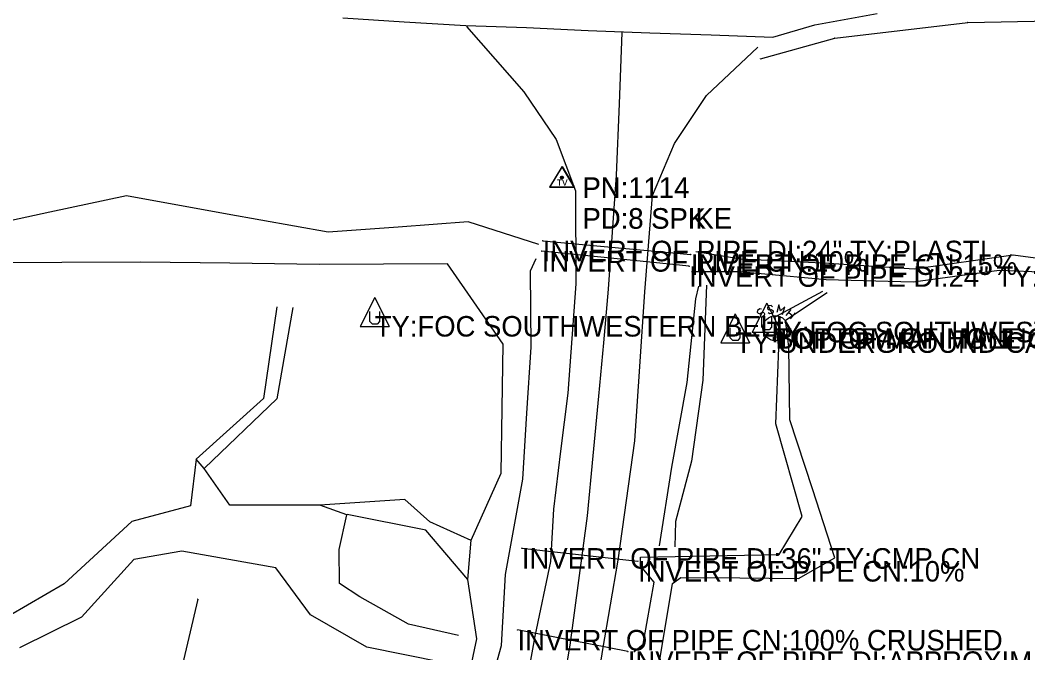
# Model space of a CAD drawing. Extents: x 976456 to 985170, y 1525951 to 1527080.
# Drawn here: x 977697.7 to 977943.1, y 1526330.3 to 1526484.4 of the extents above; entities that cross this region are included whole.
import ezdxf

# ---------------------------------------------------------------- set-up
doc = ezdxf.new("R2010")
doc.units = 0
for name, color, linetype in [('S_BREAKLINE', 7, 'Continuous'), ('S_CROSS_DRAIN', 7, 'Continuous'), ('S_CROSS_DRAIN_ANNOT', 7, 'Continuous'), ('S_DITCHLINE', 7, 'Continuous'), ('S_DRG_PT_SYM', 7, 'Continuous'), ('S_EDGE_PAVEMENT', 7, 'Continuous'), ('S_GRD_PT_SYM', 7, 'Continuous'), ('S_GUARDRAIL', 7, 'Continuous'), ('S_MANHOLE_ANNOT', 7, 'Continuous'), ('S_PAVEMENT_CROWN', 7, 'Continuous'), ('S_RDW_PT_SYM', 7, 'Continuous'), ('S_SANITARY_SEWER', 7, 'Continuous'), ('S_SECONDARY_CTL', 7, 'Continuous'), ('S_SECONDARY_CTL_ANNOT', 7, 'Continuous'), ('S_SHOULDER', 7, 'Continuous'), ('S_UNDERGROUND_CABLE', 7, 'Continuous'), ('S_UTILITY_POLE_ANNOT', 7, 'Continuous'), ('S_UTL_PT_SYM', 7, 'Continuous')]:
    doc.layers.add(name, color=color, linetype=linetype)

msp = doc.modelspace()

# ---------------------------------------------------------------- linework, layer by layer
at = {"layer": 'S_BREAKLINE'}
msp.add_line((977740.93, 1526343.34), (977728.22, 1526288.65), dxfattribs=at)
at = {"layer": 'S_CROSS_DRAIN'}
for p, q in [((977824.96, 1526430.66), (977861.01, 1526427.33)), ((977860.63, 1526424.44), (977824.71, 1526428.13)), ((977819.89, 1526355.78), (977848.16, 1526352.64)), ((977845.69, 1526330.63), (977818.83, 1526335.85))]:
    msp.add_line(p, q, dxfattribs=at)
at = {"layer": 'S_DITCHLINE'}
for points in [[(977824.01, 1526429.76), (977806.83, 1526435.23), (977789.76, 1526433.97), (977772.69, 1526432.72), (977748.13, 1526437.15), (977723.57, 1526441.59), (977704.89, 1526437.58), (977686.21, 1526433.57)], [(978029.35, 1526436.22), (978017.97, 1526427.26), (978002.04, 1526427.7), (977986.11, 1526428.13), (977972.06, 1526422.75), (977955.81, 1526424.94), (977939.55, 1526427.12), (977915.43, 1526423.73), (977894.67, 1526425.09), (977873.2, 1526426.21), (977862.22, 1526427.92)], [(977861.21, 1526423.15), (977872.89, 1526423.19), (977894, 1526421.24), (977915.17, 1526420.65), (977936.11, 1526423.49), (977952.01, 1526422.85), (977967.92, 1526422.22), (977976.62, 1526420.59), (977994.52, 1526423.18), (978016.54, 1526422.99), (978031.46, 1526432.01)], [(977803.87, 1526309.92), (977808.88, 1526333.69), (977806.74, 1526348.14), (977807.54, 1526357.7), (977814.88, 1526374.06), (977815.09, 1526389.76), (977815.3, 1526405.46), (977801.81, 1526425), (977786.16, 1526424.94), (977770.5, 1526424.88), (977748.75, 1526425.18), (977727.01, 1526425.48), (977707.82, 1526425.38), (977688.64, 1526425.27)], [(977808.39, 1526308.74), (977814.91, 1526332.03), (977815.86, 1526349.35), (977820.11, 1526372.61), (977821.12, 1526388.66), (977822.13, 1526404.71), (977822, 1526423.32), (977823.34, 1526426.37)], [(977853.4, 1526356.35), (977856.43, 1526375.48), (977860.13, 1526396.13), (977862.25, 1526416.51), (977862.98, 1526419.61)], [(977864.85, 1526419.8), (977863.93, 1526396.73), (977861.18, 1526376.96), (977857.26, 1526362.29), (977857.14, 1526356.11)], [(977847.16, 1526330.52), (977849.42, 1526332.41), (977852.1, 1526347.5), (977848.81, 1526351.45), (977848.81, 1526353.59), (977865.66, 1526353.92), (977882.51, 1526354.26), (977888.16, 1526363.46), (977881.77, 1526386.04), (977882.5, 1526404.6), (977881.56, 1526412.16), (977893.17, 1526418.4)], [(977847.83, 1526301.04), (977850.45, 1526313.6), (977853.06, 1526326.17), (977856.57, 1526347.16), (977858.63, 1526348.63), (977872.94, 1526348.52), (977887.25, 1526348.41), (977896.12, 1526353.4), (977890.63, 1526370.24), (977885.14, 1526387.07), (977884.92, 1526404.81), (977884.08, 1526411.28), (977894.26, 1526418.08)], [(977760.18, 1526414.57), (977756.94, 1526392.26), (977740.53, 1526377.44)], [(977764.09, 1526414.37), (977760.22, 1526392.12), (977742.56, 1526375.25)], [(977804.41, 1526334.54), (977792.3, 1526337.23), (977780.42, 1526343.88), (977775.43, 1526347.17), (977775.37, 1526355.41), (977777.24, 1526363.86), (977770.71, 1526366.26), (977748.79, 1526366.23), (977742.52, 1526375.22), (977740.54, 1526377.45), (977739.18, 1526366.08), (977724.89, 1526362.3), (977708.4, 1526347.08), (977690.48, 1526336.73)], [(977807.52, 1526357.61), (977797.49, 1526362.17), (977791.37, 1526367.64), (977770.7, 1526366.24)], [(977806.74, 1526348.14), (977796.52, 1526360.14), (977777.31, 1526363.99)], [(977804.61, 1526322.43), (977800.62, 1526327.94), (977782.14, 1526331.65), (977768.39, 1526339.53), (977759.99, 1526350.97), (977737.1, 1526355.06), (977725.38, 1526353.03), (977712.6, 1526339), (977697.5, 1526331.47)]]:
    msp.add_lwpolyline(points, dxfattribs=at)
at = {"layer": 'S_DRG_PT_SYM'}
for points in [[(977824.96, 1526430.66), (977824.96, 1526430.71), (977824.96, 1526430.66), (977824.91, 1526430.66), (977824.96, 1526430.66), (977824.96, 1526430.61), (977824.96, 1526430.66), (977825.01, 1526430.66)], [(977824.71, 1526428.13), (977824.71, 1526428.18), (977824.71, 1526428.13), (977824.66, 1526428.13), (977824.71, 1526428.13), (977824.71, 1526428.08), (977824.71, 1526428.13), (977824.76, 1526428.13)], [(977861.01, 1526427.33), (977861.01, 1526427.38), (977861.01, 1526427.33), (977860.96, 1526427.33), (977861.01, 1526427.33), (977861.01, 1526427.28), (977861.01, 1526427.33), (977861.06, 1526427.33)], [(977860.63, 1526424.44), (977860.63, 1526424.49), (977860.63, 1526424.44), (977860.58, 1526424.44), (977860.63, 1526424.44), (977860.63, 1526424.39), (977860.63, 1526424.44), (977860.68, 1526424.44)], [(977819.89, 1526355.78), (977819.89, 1526355.83), (977819.89, 1526355.78), (977819.84, 1526355.78), (977819.89, 1526355.78), (977819.89, 1526355.73), (977819.89, 1526355.78), (977819.94, 1526355.78)], [(977848.16, 1526352.64), (977848.16, 1526352.69), (977848.16, 1526352.64), (977848.11, 1526352.64), (977848.16, 1526352.64), (977848.16, 1526352.59), (977848.16, 1526352.64), (977848.21, 1526352.64)], [(977818.83, 1526335.85), (977818.83, 1526335.9), (977818.83, 1526335.85), (977818.78, 1526335.85), (977818.83, 1526335.85), (977818.83, 1526335.8), (977818.83, 1526335.85), (977818.88, 1526335.85)], [(977845.69, 1526330.63), (977845.69, 1526330.68), (977845.69, 1526330.63), (977845.64, 1526330.63), (977845.69, 1526330.63), (977845.69, 1526330.58), (977845.69, 1526330.63), (977845.74, 1526330.63)]]:
    msp.add_lwpolyline(points, dxfattribs=at)
at = {"layer": 'S_EDGE_PAVEMENT'}
for points in [[(977806.37, 1526482.87), (977820.39, 1526466.97), (977828.21, 1526455.31), (977832.92, 1526442.85), (977832.99, 1526420.15), (977832.01, 1526406.85), (977831.04, 1526393.54), (977829.31, 1526379.42), (977827.58, 1526365.3), (977826.83, 1526352.54), (977823.07, 1526334.32), (977820.44, 1526319.89), (977820.11, 1526318.04)], [(977836.99, 1526314.48), (977839.59, 1526331.09), (977843.36, 1526352.86), (977845.38, 1526367.38), (977847.41, 1526381.91), (977848.61, 1526400.06), (977849.81, 1526418.21), (977851.7, 1526441.64), (977857.03, 1526454.35), (977864.88, 1526466), (977877.36, 1526477.82)]]:
    msp.add_lwpolyline(points, dxfattribs=at)
at = {"layer": 'S_GRD_PT_SYM'}
msp.add_lwpolyline([(977740.93, 1526343.34), (977740.93, 1526343.39), (977740.93, 1526343.34), (977740.88, 1526343.34), (977740.93, 1526343.34), (977740.93, 1526343.29), (977740.93, 1526343.34), (977740.98, 1526343.34)], dxfattribs=at)
at = {"layer": 'S_GUARDRAIL'}
for p, q in [((977896.06, 1526480.01), (977928.47, 1526483.86)), ((977928.47, 1526483.86), (977954.58, 1526484.3)), ((977878.03, 1526474.98), (977896.06, 1526480.01))]:
    msp.add_line(p, q, dxfattribs=at)
at = {"layer": 'S_PAVEMENT_CROWN'}
msp.add_lwpolyline([(977844.21, 1526481.41), (977843.54, 1526464.03), (977842.87, 1526446.65), (977841.9, 1526432.77), (977840.93, 1526418.89), (977839.74, 1526405.83), (977838.55, 1526392.78), (977837.18, 1526378.23), (977835.8, 1526363.67), (977833.69, 1526347.92), (977831.58, 1526332.17), (977829.1, 1526317.87), (977826.61, 1526303.58), (977821.41, 1526279.65), (977816.2, 1526255.72), (977811.81, 1526238.51), (977807.43, 1526221.29), (977803.88, 1526208.91), (977800.34, 1526196.52), (977796.79, 1526184.14), (977793.25, 1526171.75), (977786.88, 1526150.07), (977780.5, 1526128.38)], dxfattribs=at)
at = {"layer": 'S_RDW_PT_SYM'}
for points in [[(977928.47, 1526483.86), (977928.47, 1526483.91), (977928.47, 1526483.86), (977928.42, 1526483.86), (977928.47, 1526483.86), (977928.47, 1526483.81), (977928.47, 1526483.86), (977928.52, 1526483.86)], [(977896.06, 1526480.01), (977896.06, 1526480.06), (977896.06, 1526480.01), (977896.01, 1526480.01), (977896.06, 1526480.01), (977896.06, 1526479.96), (977896.06, 1526480.01), (977896.11, 1526480.01)], [(977878.03, 1526474.98), (977878.03, 1526475.03), (977878.03, 1526474.98), (977877.98, 1526474.98), (977878.03, 1526474.98), (977878.03, 1526474.93), (977878.03, 1526474.98), (977878.08, 1526474.98)]]:
    msp.add_lwpolyline(points, dxfattribs=at)
at = {"layer": 'S_SANITARY_SEWER'}
for p, q in [((977877.29, 1526413.66), (977877.21, 1526413.27)), ((977877.21, 1526413.27), (977877.4, 1526413)), ((977877.83, 1526414.04), (977877.29, 1526413.66)), ((977877.4, 1526413), (977877.83, 1526412.88)), ((977878.26, 1526413.97), (977877.83, 1526414.04)), ((977877.83, 1526412.88), (977878.37, 1526413.23)), ((977878.37, 1526412.07), (977877.98, 1526412.15)), ((977878.37, 1526413.23), (977878.84, 1526413.15)), ((977878.91, 1526412.46), (977878.37, 1526412.07)), ((977878.84, 1526413.15), (977878.99, 1526412.88)), ((977878.99, 1526412.88), (977878.91, 1526412.46)), ((977884.26, 1526412.42), (977885.5, 1526413.89)), ((977884.92, 1526413.19), (977885.89, 1526412.38)), ((977886.47, 1526413.08), (977885.23, 1526411.6))]:
    msp.add_line(p, q, dxfattribs=at)
for points in [[(977880.93, 1526414.59), (977880.58, 1526414.86), (977879.92, 1526414.78), (977879.69, 1526414.43), (977879.73, 1526414.12), (977880.08, 1526413.81), (977880.7, 1526413.93), (977881.08, 1526413.62), (977881.12, 1526413.31), (977880.85, 1526412.92), (977880.23, 1526412.84), (977879.88, 1526413.11)], [(977883.37, 1526412.73), (977883.91, 1526414.59), (977882.87, 1526413.58), (977882.48, 1526415.01), (977881.94, 1526413.15)]]:
    msp.add_lwpolyline(points, dxfattribs=at)
msp.add_circle((977881.61, 1526409.35), 3.05, dxfattribs=at)
at = {"layer": 'S_SECONDARY_CTL'}
for p, q in [((977829.67, 1526448.72), (977826.66, 1526443.76)), ((977829.67, 1526448.72), (977832.62, 1526443.76)), ((977829.63, 1526448.69), (977826.62, 1526443.74)), ((977829.63, 1526448.69), (977832.57, 1526443.74)), ((977826.62, 1526443.74), (977832.57, 1526443.74)), ((977826.66, 1526443.76), (977832.62, 1526443.76))]:
    msp.add_line(p, q, dxfattribs=at)
for centre, radius in [((977829.63, 1526446.08), 0.311), ((977829.67, 1526446.11), 0.311), ((977829.63, 1526446.08), 0.183), ((977829.67, 1526446.11), 0.183), ((977829.63, 1526446.08), 0.103), ((977829.67, 1526446.11), 0.103)]:
    msp.add_circle(centre, radius, dxfattribs=at)
at = {"layer": 'S_SHOULDER'}
msp.add_lwpolyline([(977776.26, 1526484.99), (977791.24, 1526483.97), (977806.22, 1526483.07), (977821.05, 1526482.58), (977836.03, 1526481.89), (977851.02, 1526481.29), (977866.01, 1526480.8), (977881, 1526480.22), (977891.25, 1526483.24), (977906.37, 1526485.99)], dxfattribs=at)
at = {"layer": 'S_UNDERGROUND_CABLE'}
for p, q in [((977784.05, 1526416.86), (977780.52, 1526409.77)), ((977784.05, 1526416.86), (977787.54, 1526409.77)), ((977879.51, 1526415.45), (977875.99, 1526408.36)), ((977879.51, 1526415.45), (977883, 1526408.36)), ((977782.85, 1526411.01), (977782.85, 1526413.45)), ((977785.21, 1526413.45), (977785.21, 1526411.01)), ((977871.84, 1526412.89), (977868.31, 1526405.8)), ((977871.84, 1526412.89), (977875.33, 1526405.8)), ((977878.31, 1526409.6), (977878.31, 1526412.04)), ((977880.68, 1526412.04), (977880.68, 1526409.6)), ((977780.52, 1526409.77), (977787.54, 1526409.77)), ((977783.47, 1526410.35), (977782.85, 1526411.01)), ((977784.67, 1526410.35), (977783.47, 1526410.35)), ((977785.21, 1526411.01), (977784.67, 1526410.35)), ((977870.64, 1526407.04), (977870.64, 1526409.48)), ((977873, 1526409.48), (977873, 1526407.04)), ((977878.93, 1526408.94), (977878.31, 1526409.6)), ((977880.68, 1526409.6), (977880.13, 1526408.94)), ((977871.26, 1526406.38), (977870.64, 1526407.04)), ((977873, 1526407.04), (977872.46, 1526406.38)), ((977875.99, 1526408.36), (977883, 1526408.36)), ((977880.13, 1526408.94), (977878.93, 1526408.94)), ((977868.31, 1526405.8), (977875.33, 1526405.8)), ((977872.46, 1526406.38), (977871.26, 1526406.38))]:
    msp.add_line(p, q, dxfattribs=at)
at = {"layer": 'S_UTL_PT_SYM'}
msp.add_lwpolyline([(977881.61, 1526409.35), (977881.61, 1526409.4), (977881.61, 1526409.35), (977881.56, 1526409.35), (977881.61, 1526409.35), (977881.61, 1526409.3), (977881.61, 1526409.35), (977881.66, 1526409.35)], dxfattribs=at)

# ---------------------------------------------------------------- texts
at = {"layer": 'S_CROSS_DRAIN_ANNOT'}
for s, p in [('INVERT OF PIPE DI:24" TY:PLASTI', (977824.96, 1526425.66)), ('INVERT OF PIPE CN:10%', (977824.71, 1526423.13)), ('INVERT OF PIPE CN:15%', (977861.01, 1526422.33)), ('INVERT OF PIPE DI:24" TY:PLASTI', (977860.63, 1526419.44)), ('INVERT OF PIPE DI:36" TY:CMP CN', (977819.89, 1526350.78)), ('INVERT OF PIPE CN:10%', (977848.16, 1526347.64)), ('INVERT OF PIPE CN:100% CRUSHED', (977818.83, 1526330.85)), ('INVERT OF PIPE DI:APPROXIMATE 1', (977845.69, 1526325.63))]:
    msp.add_text(s, height=5, dxfattribs=at).set_placement(p)
at = {"layer": 'S_MANHOLE_ANNOT'}
for s in ['TOP OF MANHOLE', 'BOTTOM OF MANHOLE']:
    msp.add_text(s, height=5, dxfattribs=at).set_placement((977881.61, 1526404.35))
at = {"layer": 'S_SECONDARY_CTL'}
for p in [(977828.42, 1526444.07), (977828.47, 1526444.1)]:
    msp.add_text('TV', height=1.5, rotation=360, dxfattribs=at).set_placement(p)
at = {"layer": 'S_SECONDARY_CTL_ANNOT'}
for s, p in [('PN:1114', (977834.63, 1526441.08)), ('PN:1114', (977834.67, 1526441.11)), ('PD:8 SPK', (977834.63, 1526433.58)), ('PD:8 SPIKE', (977834.67, 1526433.61))]:
    msp.add_text(s, height=5, dxfattribs=at).set_placement(p)
at = {"layer": 'S_UTILITY_POLE_ANNOT'}
for s, p in [('TY:FOC SOUTHWESTERN BELL', (977784.05, 1526407.32)), ('TY:FOC SOUTHWESTERN BELL', (977879.51, 1526405.92)), ('TY:UNDERGROUND CABLE', (977871.84, 1526403.35))]:
    msp.add_text(s, height=5, dxfattribs=at).set_placement(p)

doc.saveas('drawing.dxf')
